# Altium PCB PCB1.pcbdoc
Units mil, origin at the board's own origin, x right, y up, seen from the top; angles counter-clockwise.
Board outline 3543.31 x 1377.95 mil, 2 copper layers (Top Layer, Bottom Layer), stack 62.206 mil thick; 23 components, 15 nets, 67 pads, 4 vias.
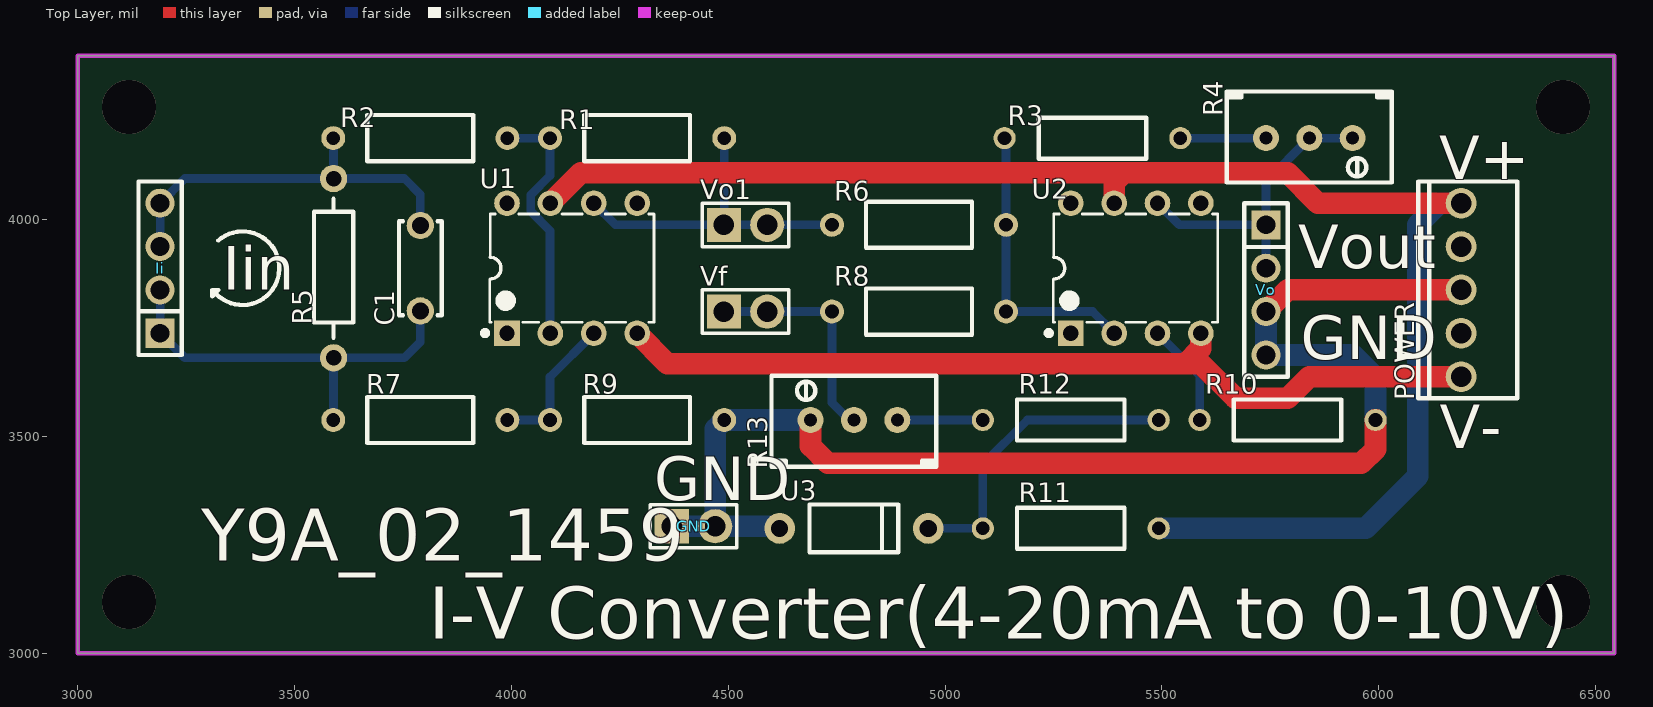
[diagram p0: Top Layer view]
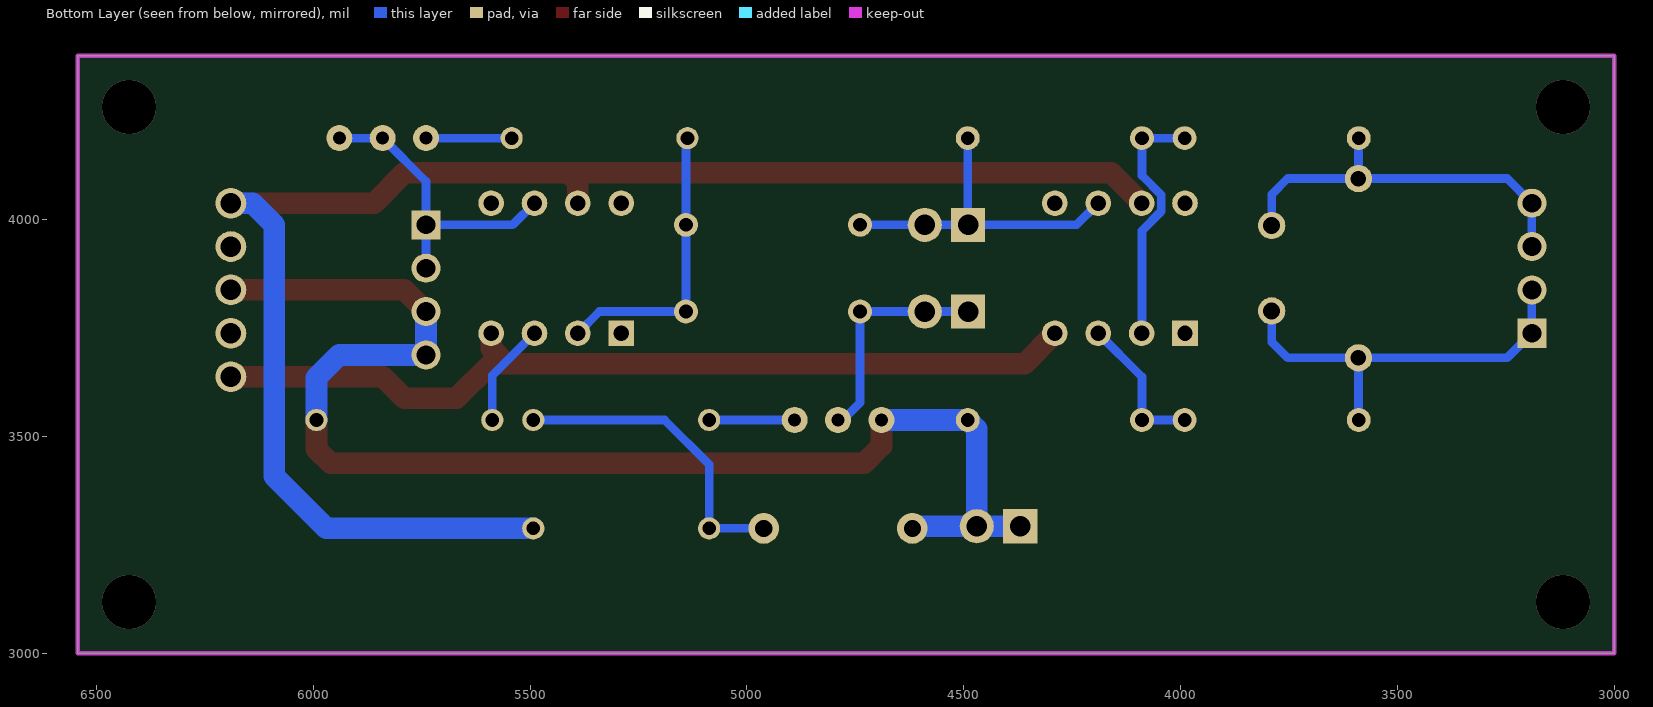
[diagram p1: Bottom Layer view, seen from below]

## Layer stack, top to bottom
Top Solder Mask Layer: solder mask 0.394, Dk 3.3
Top Layer: signal copper 1.379
Dielectric1: surface 59.449, FR4, Dk 4.5
Bottom Layer: signal copper 1.378
Bottom Solder Mask Layer: solder mask 0.394, Dk 3.3

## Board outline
3000,4377.95 6543.31,4377.95 6543.31,3000 3000,3000

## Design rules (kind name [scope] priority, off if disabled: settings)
BoardOutlineClearance copperThickness1oz [All] p0: genericclearance=10 ignorepadtopadclearanceinfootprint=FALSE except(0: Arc-SplitContinuation Track-SplitContinuation SMDPad-SplitContinuation THPad-SplitContinuation Via-SplitContinuation Fill-SplitContinuation Poly-SplitContinuation Region-SplitContinuation Text-SplitContinuation)
BoardOutlineClearance copperThickness2oz [All] p0: genericclearance=10 ignorepadtopadclearanceinfootprint=FALSE except(0: Arc-SplitContinuation Track-SplitContinuation SMDPad-SplitContinuation THPad-SplitContinuation Via-SplitContinuation Fill-SplitContinuation Poly-SplitContinuation Region-SplitContinuation Text-SplitContinuation)
BoardOutlineClearance otherClearance [All] p0: genericclearance=10 ignorepadtopadclearanceinfootprint=FALSE except(0: Arc-SplitContinuation Track-SplitContinuation SMDPad-SplitContinuation THPad-SplitContinuation Via-SplitContinuation Fill-SplitContinuation Poly-SplitContinuation Region-SplitContinuation Text-SplitContinuation)
Clearance copperThickness1oz [All] p1: gap=7 ignorepadtopadclearanceinfootprint=FALSE
Clearance copperThickness2oz [All] p1: gap=7 ignorepadtopadclearanceinfootprint=FALSE
Clearance otherClearance [All] p1: gap=7 ignorepadtopadclearanceinfootprint=FALSE
DiffPairsRouting differentialPair [All] p1: maxuncoupledlength=10 minlimit=6 maxlimit=Infinity mostfreqgap=6 toplayer_minwidth=5 toplayer_prefwidth=10 toplayer_maxwidth=100 bottomlayer_minwidth=5 bottomlayer_prefwidth=10 bottomlayer_maxwidth=100
PasteMaskExpansion pasteMaskExpansion [All] p1: expansion=0
PlaneConnect innerPlane [All] p1: planeconnectstyle=Relief reliefexpansion=20 reliefentries=4 reliefconductorwidth=10 reliefairgap=10
PolygonConnect copperRegion [All] p1: connectstyle=Relief reliefentries=4 reliefconductorwidth=10 polygonreliefangle="90 Angle" airgapwidth=10
RoutingVias viaSize [All] p1: viastyle="Through Hole" holewidth=12.0078 minholewidth=11.811 maxholewidth=248.0314 width=12.0078 minwidth=11.811 maxwidth=248.0314
SolderMaskExpansion solderMaskExpansion [All] p1: useseparateexpansions=TRUE expansion=2 expansionbottom=2
Width copperThickness1oz [All] p1: maxlimit=100 minlimit=5 preferedwidth=10
Width copperThickness2oz [All] p1: maxlimit=100 minlimit=8 preferedwidth=10

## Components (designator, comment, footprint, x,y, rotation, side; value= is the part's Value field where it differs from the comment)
C1 "" CAP-TH_L5.5-W2.5-P5.00-D1.0 3790,3887.95 r90 top
GND "" HDR-TH_2P-P2.54-V-M 4420,3292.95 r0 top
Ii "" HDR-TH_4P-P2.54-V-M 3190,3887.95 r90 top
POWER "" CONN-TH_5P-P2.54_KH-HX2.54-05Z 6190,3837.95 r90 top
R1 "" RES-TH_BD2.7-L6.2-P10.20-D0.4 4290,4187.95 r0 top
R2 "" RES-TH_BD2.7-L6.2-P10.20-D0.4 3790,4187.95 r0 top
R3 "" RES-TH_BD2.4-L6.3-P10.30-D0.6 5340,4187.95 r0 top
R4 "" RES-ADJ-TH_3296W 5840,4187.95 r270 top
R5 "" RES-TH_BD2.2-L6.5-P10.50-D0.6 3590,3887.95 r90 top
R6 "" RES-TH_BD2.7-L6.2-P10.20-D0.4 4940,3987.95 r0 top
R7 "" RES-TH_BD2.7-L6.2-P10.20-D0.4 3790,3537.95 r0 top
R8 "" RES-TH_BD2.7-L6.2-P10.20-D0.4 4940,3787.95 r0 top
R9 "" RES-TH_BD2.7-L6.2-P10.20-D0.4 4290,3537.95 r180 top
R10 "" RES-TH_BD2.4-L6.3-P10.30-D0.6 5790,3537.95 r180 top
R11 "" RES-TH_BD2.4-L6.3-P10.30-D0.6 5290,3287.95 r180 top
R12 "" RES-TH_BD2.4-L6.3-P10.30-D0.6 5290,3537.95 r180 top
R13 "" RES-ADJ-TH_3296W 4790,3537.95 r90 top
U1 "" DIP-8_L9.6-W6.4-P2.54-LS7.6-BL-1 4140,3887.95 r0 top
U2 "" DIP-8_L9.6-W6.4-P2.54-LS7.6-BL-1 5440,3887.95 r0 top
U3 "" DO-41_BD2.4-L4.7-P8.70-D0.9-RD 4790,3287.95 r180 top
Vf "" HDR-TH_2P-P2.54-V-M 4540,3787.95 r0 top
Vo "" HDR-TH_4P-P2.54-V-M 5740,3837.95 r270 top
Vo1 "" HDR-TH_2P-P2.54-V-M 4540,3987.95 r0 top

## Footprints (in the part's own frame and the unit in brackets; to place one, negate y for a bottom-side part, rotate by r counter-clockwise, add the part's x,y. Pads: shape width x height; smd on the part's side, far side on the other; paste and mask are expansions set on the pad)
CAP-TH_L5.5-W2.5-P5.00-D1.0 [mm]
  round 1.6 hole 1: 1(-2.5,0) 2(2.5,0)
  silkscreen extent -2.75,-1.25 2.75,1.25
CONN-TH_5P-P2.54_KH-HX2.54-05Z [mm]
  round 1.8 hole 1.2: 1(-5.08,0) 2(-2.54,0) 3(0,0) 4(2.54,0) 5(5.08,0)
  silkscreen extent -6.35,-3.3 6.35,2.5
DIP-8_L9.6-W6.4-P2.54-LS7.6-BL-1 [mm]
  rect 1.5x1.5 hole 0.9: 1(-3.81,-3.81)
  round 1.5 hole 0.9: 2(-1.27,-3.81) 3(1.27,-3.81) 4(3.81,-3.81) 5(3.81,3.81) 6(1.27,3.81) 7(-1.27,3.81) 8(-3.81,3.81)
  silkscreen extent -5.25,-3.95 4.8,3.17
DO-41_BD2.4-L4.7-P8.70-D0.9-RD [mm]
  round 1.8 hole 1: 1(-4.35,0) 2(4.35,0)
  silkscreen extent -2.6,-1.4 2.6,1.4
HDR-TH_2P-P2.54-V-M [mm]
  rect 2x2 hole 1.2: 1(-1.27,0)
  round 2 hole 1.2: 2(1.27,0)
  silkscreen extent -2.54,-1.27 2.54,1.27
HDR-TH_4P-P2.54-V-M [mm]
  rect 1.7x1.7 hole 1.1: 1(-3.81,0)
  round 1.7 hole 1.1: 2(-1.27,0) 3(1.27,0) 4(3.81,0)
  silkscreen extent -5.08,-1.27 5.08,1.27
RES-ADJ-TH_3296W [mil]
  round 60 hole 30: 1(0,100.01) 2(0,0.01) 3(0,-99.99)
  silkscreen extent -108,-190 102,190
RES-TH_BD2.2-L6.5-P10.50-D0.6 [mm]
  round 1.6 hole 0.914: 1(-5.25,0) 2(5.25,0)
  silkscreen extent -4.06,-1.14 4.06,1.14
RES-TH_BD2.4-L6.3-P10.30-D0.6 [mm]
  round 1.3 hole 0.8: 1(-5.15,0) 2(5.15,0)
  silkscreen extent -3.15,-1.2 3.15,1.2
RES-TH_BD2.7-L6.2-P10.20-D0.4 [mm]
  round 1.4 hole 0.8 copper offset 0,0: 1(-5.1,0) 2(5.1,0)
  silkscreen extent -3.1,-1.35 3.1,1.35

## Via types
v1: diameter 125, hole 125, Top Layer to Bottom Layer, 4 vias

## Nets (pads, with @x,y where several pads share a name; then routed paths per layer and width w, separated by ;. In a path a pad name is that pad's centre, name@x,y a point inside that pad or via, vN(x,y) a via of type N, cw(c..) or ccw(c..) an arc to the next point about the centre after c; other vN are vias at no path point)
$1N4: R7.2 R9.2 U1.3 | length 340.2
  Bottom Layer w20: R7.2 R9.2 4089.21,3637.16 U1.3
$1N6: C1.1 Ii.1 Ii.2 R5.1 R7.1 | length 953.9
  Bottom Layer w20: Ii.2 Ii.1 3246.7,3681.26 R5.1 ; R7.1 3590,3538.74 R5.1 ; C1.1 3790,3717.95 3753.3,3681.26 R5.1
$1N9: R1.1 R2.2 U1.2 | length 585.8
  Bottom Layer w20: R2.2 R1.1 4089.21,4101.53 4044.49,4056.8 4044.49,4019.1 4089.21,3974.38 4089.21,3738.74 U1.2
$1N10: C1.2 Ii.3 Ii.4 R2.1 R5.2 | length 903.9
  Bottom Layer w20: Ii.3 Ii.4 3246.7,4094.65 R5.2 ; R2.1 3590,4187.16 R5.2 ; C1.2 3790,4057.95 3753.3,4094.65 R5.2
$1N11: R1.2 R6.1 U1.6 Vo1.1 Vo1.2 | length 770.2
  Bottom Layer w20: U1.6 4240,3987.95 Vo1.1 ; R1.2 4490.79,3988.74 Vo1.1 ; R6.1 Vo1.2 Vo1.1
$1N13: R3.1 R6.2 R8.2 U2.2 | length 671.4
  Bottom Layer w20: R3.1 5140.79,4184.4 R6.2 R8.2 5340,3787.95 U2.2
$1N15: R10.2 U2.3 | length 240.3
  Bottom Layer w20: U2.3 5587.24,3640.71 R10.2
$1N18: R3.2 R4.3 | length 197.2
  Bottom Layer w20: R3.2 R4.3
$1N19: R4.1 R4.2 U2.6 Vo.1 Vo.2 | length 712.1
  Bottom Layer w20: U2.6 5540,3987.95 Vo.1 ; Vo.2 Vo.1 ; R4.1 R4.2 5740,4087.95 Vo.1
$1N22: R8.1 R13.2 Vf.1 Vf.2 | length 526.6
  Bottom Layer w20: Vf.1 Vf.2 R8.1 4739.21,3577.95 4779.21,3537.95 R13.2
$1N25: R11.2 R12.1 U3.1 | length 721.3
  Bottom Layer w20: U3.1 R11.2 5087.24,3435.19 5190,3537.95 R12.1
$1N36: R12.2 R13.3 | length 197.2
  Bottom Layer w20: R13.3 R12.2
GND: GND.1 GND.2 POWER.3 R9.1 R10.1 R13.1 U3.2 Vo.3 Vo.4 | length 3106.3
  Top Layer w50: R13.1 4690,3477.95 4730,3437.95 5960,3437.95 5992.76,3470.71 R10.1 ; Vo.3 5790,3837.95 POWER.3
  Bottom Layer w50: GND.1 GND.2 ; U3.2 4613.74,3292.95 GND.2 ; R13.1 R9.1 4470,3517.16 GND.2 ; Vo.3 Vo.4 5940,3687.95 5992.76,3635.19 R10.1
VCC+: POWER.5 R11.1 U1.7 U2.7 | length 3584.9
  Top Layer w50: U1.7 4160,4107.95 5412.3,4107.95 ; U2.7 5390,4085.66 5412.3,4107.95 ; POWER.5 5860,4037.95 5790,4107.95 5412.3,4107.95
  Bottom Layer w50: R11.1 5970,3287.95 6090,3407.95 6090,3987.95 6140,4037.95 POWER.5
VCC-: POWER.1 U1.4 U2.4 | length 2067.3
  Top Layer w50: U1.4 4360,3667.95 5555.01,3667.95 ; U2.4 5590,3702.94 5555.01,3667.95 ; POWER.1 5840,3637.95 5790,3587.95 5670,3587.95 5590,3667.95 5555.01,3667.95
pads on no net: POWER.2 POWER.4 U1.1 U1.5 U1.8 U2.1 U2.5 U2.8
copper on no net:
  other v1: 3118.11,3118.11 6425.2,3118.11 3118.11,4259.84 6425.2,4259.84

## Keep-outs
Board Outline Layer:
  the board outline again, w10

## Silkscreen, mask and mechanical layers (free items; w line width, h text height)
Top Silkscreen Layer:
  lines w10: 3320,3827.95 ccw(c3380,3887.95) 3324.12,3951.81 ; 3310,3822.95 3310,3837.67 3324.72,3837.67 3310,3822.95
  text "V+" at 6140,4092.95 h100
  text "Vout" at 5815,3887.95 h100
  text "Iin" at 3335,3837.95 h100
  text "GND" at 5820,3677.95 h100
  text "V-" at 6141.25,3472.95 h100
  text "GND" at 4330,3352.95 h100
  text "Y9A_02_1459" at 3285,3212.95 h120
  text "I-V Converter(4-20mA to 0-10V)" at 3810,3032.95 h120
